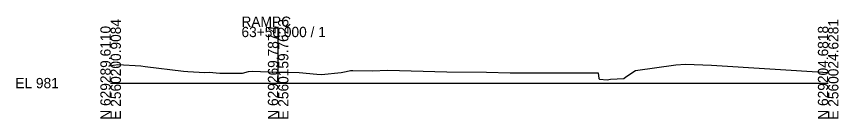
# Model space of a CAD drawing. Extents: x -985277 to -984049, y -985285 to -975702.
# Drawn here: x -984277.3 to -984053.1, y -983261.3 to -983233.4 of the extents above; entities that cross this region are included whole.
import ezdxf

# ---------------------------------------------------------------- set-up
doc = ezdxf.new("R2010")
doc.units = 0
doc.layers.add('DESIGN - SHEET - Light Grid', color=7, linetype='Continuous')
doc.layers.add('SURVEY - GROUND - Top of Rock Layer', color=7, linetype='Continuous')

msp = doc.modelspace()

# ---------------------------------------------------------------- linework, layer by layer
at = {"layer": 'DESIGN - SHEET - Light Grid'}
for p, q in [((-984205.96, -983251.64), (-984205.96, -983236.29)), ((-984251.64, -983251.64), (-984205.96, -983251.64)), ((-984205.96, -983251.64), (-984055.96, -983251.64))]:
    msp.add_line(p, q, dxfattribs=at)
at = {"layer": 'SURVEY - GROUND - Top of Rock Layer'}
msp.add_lwpolyline([(-984251.64, -983246.97), (-984250.88, -983246.79), (-984249.71, -983246.58), (-984243.38, -983246.96), (-984242.19, -983247.08), (-984231.78, -983248.39), (-984230.61, -983248.52), (-984225.96, -983248.77), (-984224.75, -983248.65), (-984221.85, -983248.92), (-984215.67, -983248.94), (-984214.07, -983248.44), (-984212.88, -983248.39), (-984206.5, -983248.68), (-984205.96, -983248.68), (-984204.82, -983248.68), (-984200.2, -983248.78), (-984195.4, -983249.24), (-984194.09, -983249.27), (-984188.81, -983248.76), (-984187.39, -983248.47), (-984186.23, -983248.25), (-984185.63, -983248.2), (-984180.25, -983248.32), (-984176.09, -983248.12), (-984159.93, -983248.57), (-984149.13, -983248.68), (-984142.64, -983248.82), (-984118.64, -983248.87), (-984118.5, -983250.37), (-984118.28, -983250.53), (-984116.22, -983250.74), (-984115.35, -983250.6), (-984111.65, -983250.4), (-984111.18, -983249.95), (-984108.53, -983248.23), (-984097.49, -983246.65), (-984094.84, -983246.52), (-984087.75, -983246.72), (-984055.96, -983248.73)], dxfattribs=at)

# ---------------------------------------------------------------- texts
at = {"layer": 'DESIGN - SHEET - Light Grid'}
for s, p in [('RAMPC', (-984215.96, -983236.29)), ('63+50.000 / 1', (-984215.96, -983239.09)), ('EL 981', (-984277.64, -983253.04))]:
    msp.add_text(s, height=2.8, dxfattribs=at).set_placement(p)
for s, p in [('E 2560200.9084', (-984248.84, -983261.64)), ('E 2560159.7623', (-984203.16, -983261.64)), ('E 2560024.6281', (-984053.16, -983261.64)), ('N 629289.6110', (-984251.64, -983261.64)), ('N 629269.7874', (-984205.96, -983261.64)), ('N 629204.6818', (-984055.96, -983261.64))]:
    msp.add_text(s, height=2.8, rotation=90, dxfattribs=at).set_placement(p)

doc.saveas('drawing.dxf')
